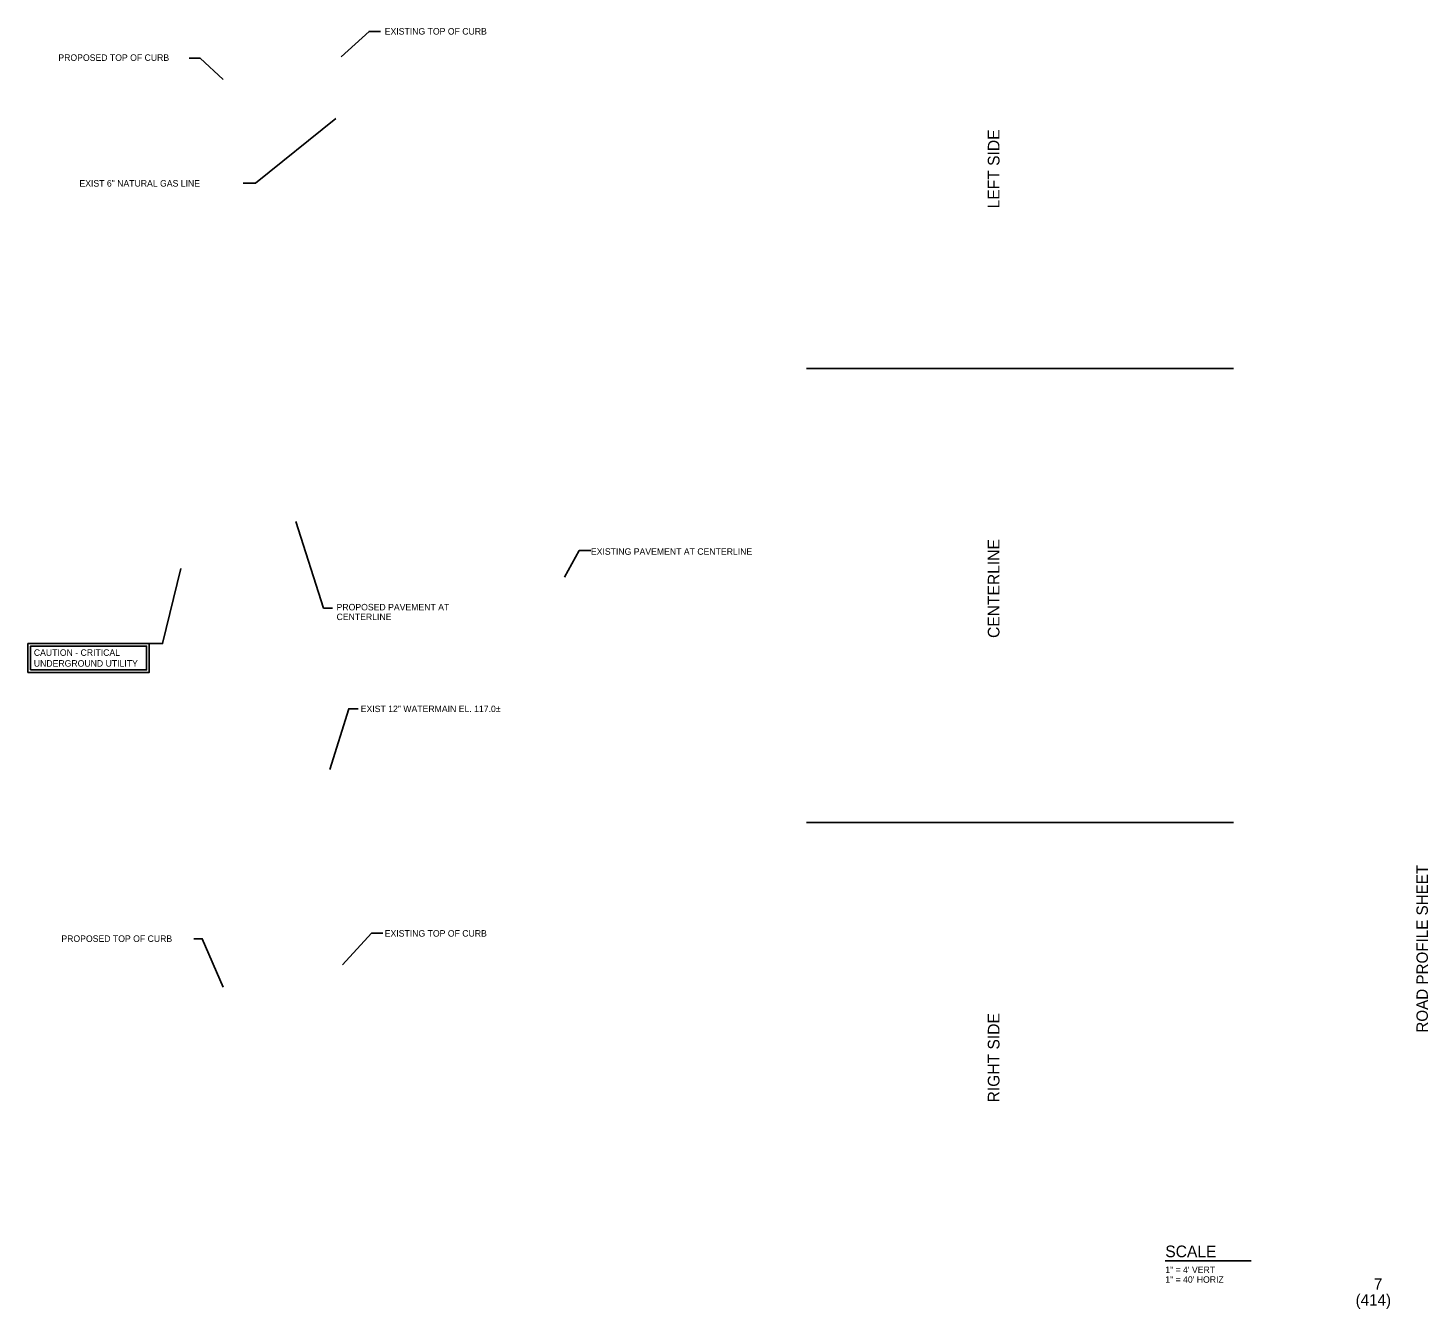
# Model space of a CAD drawing. Extents: x 13484372 to 13485236, y 312280 to 313070.
import ezdxf

# ---------------------------------------------------------------- set-up
doc = ezdxf.new("R2010")
doc.units = 0
for name, color, linetype in [('BORDER', 7, 'Continuous'), ('G-ANNO-TTLB', 7, 'Continuous'), ('Repaired by FileFixer 4000000', 7, 'Continuous')]:
    doc.layers.add(name, color=color, linetype=linetype)

msp = doc.modelspace()

# ---------------------------------------------------------------- linework, layer by layer
at = {"layer": 'BORDER'}
for p, q in [((13484852.83, 312860.12), (13485116.26, 312860.12)), ((13484372.35, 312672.63), (13484372.35, 312690.5)), ((13484372.35, 312690.5), (13484447.17, 312690.5)), ((13484373.95, 312674.23), (13484373.95, 312688.9)), ((13484373.95, 312688.9), (13484445.57, 312688.9)), ((13484373.95, 312674.23), (13484373.95, 312688.9)), ((13484373.95, 312688.9), (13484445.57, 312688.9)), ((13484445.57, 312688.9), (13484445.57, 312674.23)), ((13484445.57, 312688.9), (13484445.57, 312674.23)), ((13484447.17, 312690.5), (13484447.17, 312672.63)), ((13484447.17, 312672.63), (13484372.35, 312672.63)), ((13484445.57, 312674.23), (13484373.95, 312674.23)), ((13484445.57, 312674.23), (13484373.95, 312674.23)), ((13484852.83, 312580.12), (13485116.26, 312580.12)), ((13485074.14, 312309.72), (13485127.18, 312309.72))]:
    msp.add_line(p, q, dxfattribs=at)
for points in [[(13484471.76, 313051.58), (13484478.68, 313051.58), (13484492.83, 313038.54)], [(13484505.12, 312974.43), (13484512.75, 312974.43), (13484562.3, 313014.45)], [(13484560.26, 312712.34), (13484554.76, 312712.34), (13484537.64, 312765.78)], [(13484447.17, 312690.5), (13484455.39, 312690.5), (13484466.71, 312736.84)], [(13484372.35, 312690.5), (13484372.35, 312672.63), (13484447.17, 312672.63), (13484447.17, 312690.5), (13484372.35, 312690.5)], [(13484373.95, 312674.23), (13484373.95, 312688.9), (13484445.57, 312688.9), (13484445.57, 312674.23), (13484373.95, 312674.23)], [(13484576.06, 312650.21), (13484570.24, 312650.21), (13484558.61, 312612.68)], [(13484474.74, 312508.32), (13484479.92, 312508.32), (13484492.83, 312478.54)]]:
    msp.add_lwpolyline(points, dxfattribs=at)
at = {"layer": 'Repaired by FileFixer 4000000'}
for points in [[(13484589.89, 313068.16), (13484582.87, 313068.16), (13484565.61, 313052.36)], [(13484719.72, 312747.83), (13484712.48, 312747.83), (13484703.42, 312731.47)], [(13484591.34, 312511.79), (13484584.41, 312511.79), (13484566.41, 312492.34)]]:
    msp.add_lwpolyline(points, dxfattribs=at)

# ---------------------------------------------------------------- texts
at = {"layer": 'BORDER'}
for s, height, p in [('PROPOSED TOP OF CURB', 4, (13484391.1, 313049.96)), ('EXIST 6" NATURAL GAS LINE', 4, (13484404.09, 312972.38)), ('PROPOSED PAVEMENT AT ', 4, (13484562.76, 312710.95)), ('CENTERLINE', 4, (13484562.76, 312704.95)), ('CAUTION - CRITICAL ', 4, (13484375.95, 312682.9)), ('UNDERGROUND UTILITY', 4, (13484375.95, 312676.23)), ('EXIST 12" WATERMAIN EL. 117.0%%P', 4, (13484577.68, 312648.19)), ('PROPOSED TOP OF CURB', 4, (13484392.96, 312506.43)), ('SCALE', 7.2, (13485074.14, 312311.88)), ('1" = 4\' VERT', 4, (13485074.14, 312302.13)), ('1" = 40\' HORIZ', 4, (13485074.14, 312296.13))]:
    msp.add_text(s, height=height, dxfattribs=at).set_placement(p)
for s, p in [('LEFT SIDE', (13484971.82, 312958.96)), ('CENTERLINE', (13484971.82, 312693.92)), ('RIGHT SIDE', (13484971.82, 312407.38))]:
    msp.add_text(s, height=7.2, rotation=90, dxfattribs=at).set_placement(p)
at = {"layer": 'G-ANNO-TTLB'}
msp.add_text('ROAD PROFILE SHEET', height=7, rotation=90, dxfattribs=at).set_placement((13485236.15, 312450.43))
for s, p in [('7', (13485202.86, 312291.82)), ('(414)', (13485191.58, 312282.05))]:
    msp.add_text(s, height=7, dxfattribs=at).set_placement(p)
at = {"layer": 'Repaired by FileFixer 4000000'}
for s, p in [('EXISTING TOP OF CURB', (13484592.48, 313066.17)), ('EXISTING PAVEMENT AT CENTERLINE', (13484719.69, 312745.24)), ('EXISTING TOP OF CURB', (13484592.48, 312509.67))]:
    msp.add_text(s, height=4, dxfattribs=at).set_placement(p)

doc.saveas('drawing.dxf')
